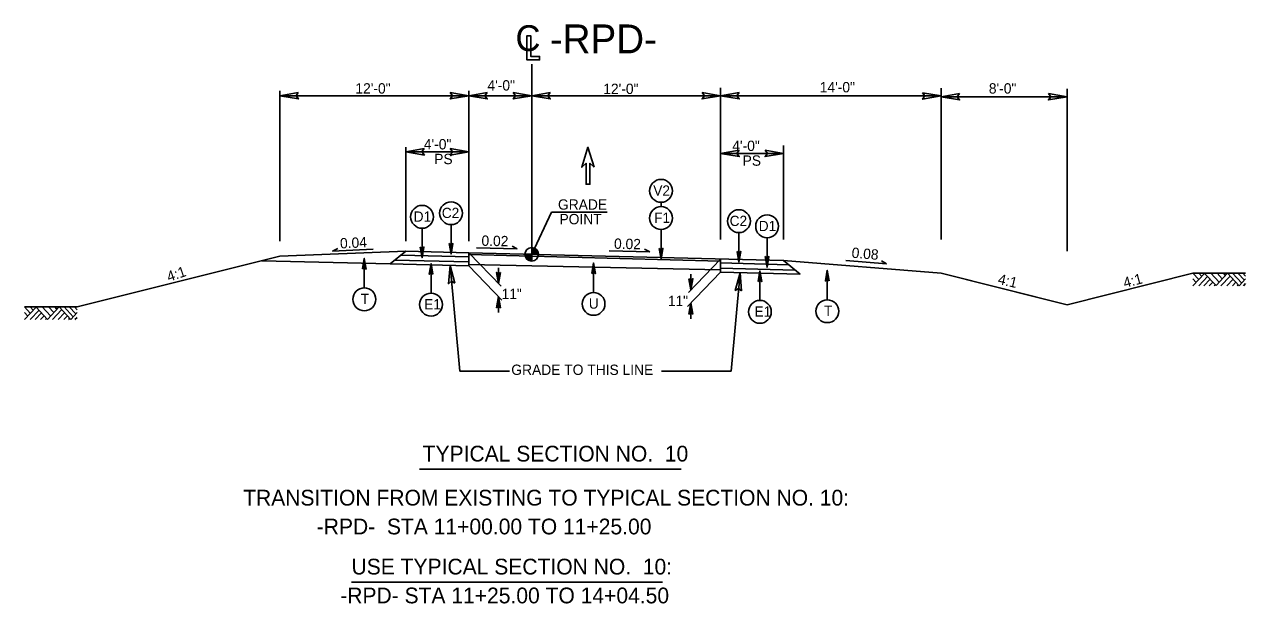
# Model space of a CAD drawing. Extents: x 1901582 to 1902252, y 193723 to 194156.
# Drawn here: x 1902172.2 to 1902249.8, y 193731.2 to 193767.9 of the extents above; entities that cross this region are included whole.
import ezdxf

# ---------------------------------------------------------------- set-up
doc = ezdxf.new("R2010")
doc.units = 0
for name, color, linetype in [('Old_Level_1', 7, 'Continuous'), ('Old_Level_11', 7, 'Continuous'), ('Old_Level_2', 7, 'Continuous'), ('Old_Level_20', 7, 'Continuous'), ('Prop Dimension', 7, 'Continuous'), ('Prop Dimension Text', 7, 'Continuous'), ('Typical Grade Point Symbol CELL', 7, 'Continuous'), ('Typical Pavement Slope Information CELL', 7, 'Continuous'), ('Typical Slope Point Local CELL', 7, 'Continuous'), ('Typical Terminator CELL', 7, 'Continuous'), ('Typical Text Centerline CELL', 7, 'Continuous'), ('Typical Text General CELL', 7, 'Continuous'), ('Typical Text Grade Point CELL', 7, 'Continuous')]:
    doc.layers.add(name, color=color, linetype=linetype)

# ---------------------------------------------------------------- blocks, each defined once
blk = doc.blocks.new('TERMINATOR')
at = {"layer": 'Typical Terminator CELL'}
blk.add_lwpolyline([(-0.469, 0.081), (0, 0), (-0.471, -0.083), (-0.411, 0)], close=True, dxfattribs=at)

msp = doc.modelspace()

# ---------------------------------------------------------------- linework, layer by layer
at = {"layer": 'Old_Level_1'}
for p, q in [((1902230.409, 193763.35), (1902238.409, 193763.35)), ((1902238.409, 193753.553), (1902238.409, 193763.85)), ((1902188.408, 193753.223), (1902175.527, 193750.002)), ((1902196.408, 193753.543), (1902188.408, 193753.223)), ((1902196.413, 193753.543), (1902195.42, 193752.734)), ((1902196.115, 193753.3), (1902200.403, 193753.193)), ((1902196.408, 193753.543), (1902200.409, 193753.443)), ((1902216.409, 193752.905), (1902200.408, 193753.327)), ((1902200.409, 193753.443), (1902200.409, 193752.609)), ((1902200.409, 193753.443), (1902220.409, 193752.943)), ((1902200.409, 193753.443), (1902202.457, 193751.326)), ((1902187.268, 193752.938), (1902195.42, 193752.734)), ((1902195.42, 193752.734), (1902200.409, 193752.609)), ((1902195.718, 193752.976), (1902200.394, 193752.86)), ((1902199.218, 193752.639), (1902199.834, 193745.929)), ((1902200.409, 193752.609), (1902202.515, 193750.433)), ((1902202.3, 193752.489), (1902202.3, 193751.489)), ((1902216.409, 193753.043), (1902214.36, 193750.926)), ((1902216.4, 193752.459), (1902221.149, 193752.341)), ((1902216.409, 193752.219), (1902216.409, 193753.043)), ((1902216.409, 193752.793), (1902220.727, 193752.685)), ((1902220.41, 193752.943), (1902230.409, 193752.143)), ((1902220.41, 193752.943), (1902221.466, 193752.083)), ((1902216.409, 193752.209), (1902214.302, 193750.033)), ((1902214.518, 193752.089), (1902214.518, 193751.089)), ((1902216.394, 193752.209), (1902221.466, 193752.083)), ((1902217.64, 193752.178), (1902217.066, 193745.929)), ((1902230.409, 193752.143), (1902236.73, 193750.562)), ((1902202.3, 193750.656), (1902202.3, 193749.656)), ((1902214.518, 193750.256), (1902214.518, 193749.256)), ((1902203.002, 193745.929), (1902199.834, 193745.929)), ((1902217.066, 193745.929), (1902212.643, 193745.929))]:
    msp.add_line(p, q, dxfattribs=at)
for points in [[(1902216.409, 193752.367), (1902200.409, 193752.687)], [(1902230.409, 193752.143), (1902238.409, 193750.143)], [(1902246.409, 193752.143), (1902238.409, 193750.143)], [(1902246.409, 193752.143), (1902249.751, 193752.143)], [(1902172.185, 193750.002), (1902175.527, 193750.002)]]:
    msp.add_lwpolyline(points, dxfattribs=at)
at = {"layer": 'Old_Level_11'}
for p, q in [((1902204.409, 193753.343), (1902204.409, 193765.415)), ((1902212.623, 193756.647), (1902212.623, 193756.369)), ((1902197.443, 193754.998), (1902197.443, 193753.124)), ((1902199.285, 193755.229), (1902199.285, 193753.355)), ((1902212.623, 193754.919), (1902212.623, 193753.045)), ((1902217.569, 193754.723), (1902217.569, 193752.849)), ((1902219.359, 193754.398), (1902219.359, 193752.524)), ((1902193.775, 193751.211), (1902193.775, 193753.085)), ((1902198.013, 193750.878), (1902198.013, 193752.753)), ((1902208.337, 193750.921), (1902208.337, 193752.796)), ((1902218.902, 193750.418), (1902218.902, 193752.292)), ((1902223.182, 193750.456), (1902223.182, 193752.33)), ((1902246.409, 193752.143), (1902246.784, 193751.74)), ((1902246.409, 193751.338), (1902247.151, 193752.135)), ((1902246.409, 193751.781), (1902246.615, 193751.559)), ((1902246.783, 193751.338), (1902247.337, 193751.934)), ((1902246.784, 193752.143), (1902246.971, 193751.942)), ((1902247.092, 193751.338), (1902247.493, 193751.767)), ((1902247.151, 193752.135), (1902247.875, 193751.356)), ((1902247.439, 193751.338), (1902247.666, 193751.581)), ((1902247.542, 193752.143), (1902248.075, 193751.57)), ((1902247.875, 193751.356), (1902248.606, 193752.142)), ((1902247.94, 193752.143), (1902248.273, 193751.784)), ((1902248.185, 193751.338), (1902248.771, 193751.966)), ((1902248.342, 193752.143), (1902248.475, 193752)), ((1902248.555, 193751.338), (1902248.955, 193751.767)), ((1902248.606, 193752.142), (1902249.347, 193751.346)), ((1902248.921, 193751.338), (1902249.138, 193751.571)), ((1902248.928, 193752.143), (1902249.508, 193751.52)), ((1902249.261, 193752.143), (1902249.675, 193751.699)), ((1902249.347, 193751.346), (1902249.751, 193751.781)), ((1902249.581, 193752.143), (1902249.751, 193751.96)), ((1902247.75, 193751.338), (1902247.821, 193751.414)), ((1902249.216, 193751.338), (1902249.285, 193751.412)), ((1902249.617, 193751.338), (1902249.751, 193751.481)), ((1902172.185, 193750.002), (1902172.56, 193749.599)), ((1902172.185, 193749.197), (1902172.927, 193749.994)), ((1902172.56, 193750.002), (1902172.747, 193749.801)), ((1902172.927, 193749.994), (1902173.651, 193749.215)), ((1902173.318, 193750.002), (1902173.851, 193749.429)), ((1902173.651, 193749.215), (1902174.382, 193750.001)), ((1902173.716, 193750.002), (1902174.049, 193749.643)), ((1902174.118, 193750.002), (1902174.251, 193749.859)), ((1902174.382, 193750.001), (1902175.123, 193749.205)), ((1902174.704, 193750.002), (1902175.284, 193749.379)), ((1902175.037, 193750.002), (1902175.451, 193749.558)), ((1902175.357, 193750.002), (1902175.527, 193749.819)), ((1902172.185, 193749.64), (1902172.391, 193749.418)), ((1902172.559, 193749.197), (1902173.113, 193749.793)), ((1902172.868, 193749.197), (1902173.269, 193749.626)), ((1902173.215, 193749.197), (1902173.442, 193749.44)), ((1902173.526, 193749.197), (1902173.597, 193749.273)), ((1902173.961, 193749.197), (1902174.547, 193749.825)), ((1902174.331, 193749.197), (1902174.731, 193749.626)), ((1902174.697, 193749.197), (1902174.914, 193749.43)), ((1902174.992, 193749.197), (1902175.061, 193749.271)), ((1902175.123, 193749.205), (1902175.527, 193749.64)), ((1902175.393, 193749.197), (1902175.527, 193749.34)), ((1902197.27, 193739.697), (1902213.896, 193739.697)), ((1902192.962, 193732.525), (1902212.705, 193732.525))]:
    msp.add_line(p, q, dxfattribs=at)
for points in [[(1902199.169, 193754.026), (1902199.285, 193753.355), (1902199.404, 193754.03), (1902199.285, 193753.944)], [(1902193.66, 193752.413), (1902193.775, 193753.085), (1902193.895, 193752.41), (1902193.775, 193752.495)], [(1902197.327, 193753.795), (1902197.443, 193753.124), (1902197.562, 193753.799), (1902197.443, 193753.713)], [(1902212.508, 193753.716), (1902212.623, 193753.045), (1902212.743, 193753.72), (1902212.623, 193753.634)], [(1902217.453, 193753.521), (1902217.569, 193752.849), (1902217.688, 193753.524), (1902217.569, 193753.438)], [(1902219.243, 193753.195), (1902219.359, 193752.524), (1902219.478, 193753.199), (1902219.359, 193753.113)], [(1902198.129, 193752.081), (1902198.013, 193752.753), (1902197.894, 193752.077), (1902198.013, 193752.163)], [(1902208.221, 193752.124), (1902208.337, 193752.796), (1902208.456, 193752.12), (1902208.337, 193752.206)], [(1902218.786, 193751.62), (1902218.902, 193752.292), (1902219.021, 193751.617), (1902218.902, 193751.702)], [(1902223.297, 193751.659), (1902223.182, 193752.33), (1902223.062, 193751.655), (1902223.182, 193751.741)]]:
    msp.add_lwpolyline(points, close=True, dxfattribs=at)
for centre in [(1902212.623, 193757.373), (1902197.443, 193755.723), (1902199.285, 193755.954), (1902212.623, 193755.644), (1902217.569, 193755.448), (1902219.359, 193755.123), (1902193.775, 193750.486), (1902198.013, 193750.153), (1902208.337, 193750.196), (1902218.902, 193749.692), (1902223.182, 193749.731)]:
    msp.add_circle(centre, 0.725, dxfattribs=at)
at = {"layer": 'Prop Dimension'}
for p, q in [((1902216.409, 193754.278), (1902216.409, 193763.915)), ((1902188.408, 193754.178), (1902188.409, 193763.715)), ((1902200.409, 193763.415), (1902188.409, 193763.415)), ((1902200.408, 193754.178), (1902200.409, 193763.715)), ((1902204.409, 193763.415), (1902200.409, 193763.415)), ((1902216.409, 193763.415), (1902204.409, 193763.415)), ((1902216.409, 193763.415), (1902230.409, 193763.4)), ((1902230.409, 193754.277), (1902230.409, 193763.9)), ((1902196.408, 193754.178), (1902196.409, 193760.152)), ((1902220.409, 193754.277), (1902220.409, 193760.252)), ((1902200.409, 193759.852), (1902196.409, 193759.852)), ((1902216.409, 193759.752), (1902220.409, 193759.752))]:
    msp.add_line(p, q, dxfattribs=at)
msp.add_lwpolyline([(1902208.377, 193758.87), (1902208.106, 193759.12), (1902208.106, 193757.787), (1902207.856, 193757.787), (1902207.856, 193759.12), (1902207.585, 193758.87), (1902207.981, 193760.141)], close=True, dxfattribs=at)
msp.add_lwpolyline([(1902208.377, 193758.87), (1902208.106, 193759.12), (1902208.106, 193757.787), (1902207.856, 193757.787), (1902207.856, 193759.12), (1902207.585, 193758.87), (1902207.981, 193760.141)], close=True, dxfattribs=at)
at = {"layer": 'Typical Grade Point Symbol CELL'}
for p, q in [((1902203.979, 193753.343), (1902204.409, 193753.343)), ((1902204.408, 193752.913), (1902204.409, 193753.343)), ((1902204.409, 193753.343), (1902204.408, 193752.913)), ((1902204.409, 193753.343), (1902204.409, 193753.772)), ((1902204.839, 193753.343), (1902204.409, 193753.343))]:
    msp.add_line(p, q, dxfattribs=at)
for points in [[(1902203.981, 193753.343), (1902203.981, 193753.296)], [(1902203.99, 193753.343), (1902203.99, 193753.245)], [(1902203.998, 193753.343), (1902203.998, 193753.215)], [(1902204.007, 193753.343), (1902204.007, 193753.189)], [(1902204.015, 193753.343), (1902204.015, 193753.169)], [(1902204.024, 193753.343), (1902204.024, 193753.151)], [(1902204.033, 193753.343), (1902204.033, 193753.135)], [(1902204.041, 193753.343), (1902204.041, 193753.119)], [(1902204.05, 193753.343), (1902204.05, 193753.106)], [(1902204.058, 193753.343), (1902204.058, 193753.093)], [(1902204.067, 193753.343), (1902204.067, 193753.082)], [(1902204.076, 193753.343), (1902204.076, 193753.071)], [(1902204.084, 193753.343), (1902204.084, 193753.061)], [(1902204.093, 193753.343), (1902204.093, 193753.051)], [(1902204.101, 193753.343), (1902204.101, 193753.042)], [(1902204.11, 193753.343), (1902204.11, 193753.033)], [(1902204.119, 193753.343), (1902204.119, 193753.026)], [(1902204.127, 193753.343), (1902204.127, 193753.018)], [(1902204.136, 193753.343), (1902204.136, 193753.01)], [(1902204.144, 193753.343), (1902204.144, 193753.004)], [(1902204.153, 193753.343), (1902204.153, 193752.997)], [(1902204.162, 193753.343), (1902204.162, 193752.991)], [(1902204.17, 193753.343), (1902204.17, 193752.986)], [(1902204.179, 193753.343), (1902204.179, 193752.98)], [(1902204.187, 193753.343), (1902204.187, 193752.974)], [(1902204.196, 193753.343), (1902204.196, 193752.969)], [(1902204.205, 193753.343), (1902204.205, 193752.965)], [(1902204.213, 193753.343), (1902204.213, 193752.96)], [(1902204.222, 193753.343), (1902204.222, 193752.956)], [(1902204.23, 193753.343), (1902204.23, 193752.952)], [(1902204.239, 193753.343), (1902204.239, 193752.948)], [(1902204.247, 193753.343), (1902204.247, 193752.944)], [(1902204.256, 193753.343), (1902204.256, 193752.941)], [(1902204.265, 193753.343), (1902204.265, 193752.938)], [(1902204.273, 193753.343), (1902204.273, 193752.935)], [(1902204.282, 193753.343), (1902204.282, 193752.932)], [(1902204.29, 193753.343), (1902204.29, 193752.93)], [(1902204.299, 193753.343), (1902204.299, 193752.927)], [(1902204.308, 193753.343), (1902204.308, 193752.925)], [(1902204.316, 193753.343), (1902204.316, 193752.923)], [(1902204.325, 193753.343), (1902204.325, 193752.922)], [(1902204.333, 193753.343), (1902204.333, 193752.92)], [(1902204.342, 193753.343), (1902204.342, 193752.919)], [(1902204.351, 193753.343), (1902204.351, 193752.917)], [(1902204.359, 193753.343), (1902204.359, 193752.916)], [(1902204.368, 193753.343), (1902204.368, 193752.915)], [(1902204.376, 193753.343), (1902204.376, 193752.914)], [(1902204.385, 193753.343), (1902204.385, 193752.914)], [(1902204.394, 193753.343), (1902204.394, 193752.913)], [(1902204.402, 193753.343), (1902204.402, 193752.913), (1902204.402, 193752.913)], [(1902204.413, 193753.772), (1902204.413, 193753.772), (1902204.413, 193753.343)], [(1902204.421, 193753.772), (1902204.421, 193753.343)], [(1902204.43, 193753.771), (1902204.43, 193753.343)], [(1902204.438, 193753.771), (1902204.438, 193753.343)], [(1902204.447, 193753.77), (1902204.447, 193753.343)], [(1902204.456, 193753.769), (1902204.456, 193753.343)], [(1902204.464, 193753.769), (1902204.464, 193753.343)], [(1902204.473, 193753.768), (1902204.473, 193753.343)], [(1902204.481, 193753.767), (1902204.481, 193753.343)], [(1902204.49, 193753.765), (1902204.49, 193753.343)], [(1902204.499, 193753.763), (1902204.499, 193753.343)], [(1902204.507, 193753.761), (1902204.507, 193753.343)], [(1902204.516, 193753.759), (1902204.516, 193753.343)], [(1902204.524, 193753.756), (1902204.524, 193753.343)], [(1902204.533, 193753.754), (1902204.533, 193753.343)], [(1902204.542, 193753.751), (1902204.542, 193753.343)], [(1902204.55, 193753.748), (1902204.55, 193753.343)], [(1902204.559, 193753.746), (1902204.559, 193753.343)], [(1902204.567, 193753.742), (1902204.567, 193753.343)], [(1902204.576, 193753.738), (1902204.576, 193753.343)], [(1902204.585, 193753.734), (1902204.585, 193753.343)], [(1902204.593, 193753.73), (1902204.593, 193753.343)], [(1902204.602, 193753.727), (1902204.602, 193753.343)], [(1902204.61, 193753.722), (1902204.61, 193753.343)], [(1902204.619, 193753.717), (1902204.619, 193753.343)], [(1902204.628, 193753.712), (1902204.628, 193753.343)], [(1902204.636, 193753.707), (1902204.636, 193753.343)], [(1902204.645, 193753.702), (1902204.645, 193753.343)], [(1902204.653, 193753.696), (1902204.653, 193753.343)], [(1902204.662, 193753.689), (1902204.662, 193753.343)], [(1902204.67, 193753.684), (1902204.67, 193753.343)], [(1902204.679, 193753.677), (1902204.679, 193753.343)], [(1902204.688, 193753.669), (1902204.688, 193753.343)], [(1902204.696, 193753.662), (1902204.696, 193753.343)], [(1902204.705, 193753.654), (1902204.705, 193753.343)], [(1902204.713, 193753.645), (1902204.713, 193753.343)], [(1902204.722, 193753.637), (1902204.722, 193753.343)], [(1902204.731, 193753.627), (1902204.731, 193753.343)], [(1902204.739, 193753.617), (1902204.739, 193753.343)], [(1902204.748, 193753.606), (1902204.748, 193753.343)], [(1902204.756, 193753.595), (1902204.756, 193753.343)], [(1902204.765, 193753.582), (1902204.765, 193753.343)], [(1902204.774, 193753.569), (1902204.774, 193753.343)], [(1902204.782, 193753.555), (1902204.782, 193753.343)], [(1902204.791, 193753.539), (1902204.791, 193753.343)], [(1902204.799, 193753.521), (1902204.799, 193753.343)], [(1902204.808, 193753.501), (1902204.808, 193753.343)], [(1902204.817, 193753.477), (1902204.817, 193753.343)], [(1902204.825, 193753.448), (1902204.825, 193753.343)], [(1902204.834, 193753.404), (1902204.834, 193753.343)]]:
    msp.add_lwpolyline(points, dxfattribs=at)
msp.add_circle((1902204.408, 193753.343), 0.43, dxfattribs=at)
for start, end in [(179.99048, 269.99048), (359.99048, 89.99048)]:
    msp.add_arc((1902204.408, 193753.343), 0.43, start, end, dxfattribs=at)
at = {"layer": 'Typical Pavement Slope Information CELL'}
for p, q in [((1902203.488, 193753.689), (1902203.156, 193753.857)), ((1902191.757, 193753.539), (1902192.085, 193753.716)), ((1902194.341, 193753.668), (1902191.757, 193753.539)), ((1902200.901, 193753.752), (1902203.488, 193753.689)), ((1902209.319, 193753.563), (1902211.906, 193753.5)), ((1902211.906, 193753.5), (1902211.574, 193753.668)), ((1902224.368, 193752.947), (1902226.948, 193752.741)), ((1902226.948, 193752.741), (1902226.625, 193752.927))]:
    msp.add_line(p, q, dxfattribs=at)
at = {"layer": 'Typical Terminator CELL'}
for points in [[(1902189.581, 193763.617), (1902188.409, 193763.415), (1902189.587, 193763.207), (1902189.438, 193763.415)], [(1902199.237, 193763.617), (1902200.409, 193763.415), (1902199.231, 193763.207), (1902199.381, 193763.415)], [(1902201.581, 193763.617), (1902200.409, 193763.415), (1902201.587, 193763.207), (1902201.438, 193763.415)], [(1902203.237, 193763.617), (1902204.409, 193763.415), (1902203.231, 193763.207), (1902203.381, 193763.415)], [(1902205.581, 193763.617), (1902204.409, 193763.415), (1902205.587, 193763.207), (1902205.438, 193763.415)], [(1902215.237, 193763.617), (1902216.409, 193763.415), (1902215.231, 193763.207), (1902215.381, 193763.415)], [(1902217.581, 193763.617), (1902216.409, 193763.415), (1902217.587, 193763.207), (1902217.438, 193763.415)], [(1902229.237, 193763.602), (1902230.409, 193763.4), (1902229.231, 193763.192), (1902229.381, 193763.4)], [(1902231.581, 193763.552), (1902230.409, 193763.35), (1902231.587, 193763.142), (1902231.438, 193763.35)], [(1902237.237, 193763.552), (1902238.409, 193763.35), (1902237.231, 193763.142), (1902237.381, 193763.35)], [(1902197.58, 193760.054), (1902196.409, 193759.852), (1902197.587, 193759.644), (1902197.437, 193759.852)], [(1902199.237, 193760.054), (1902200.409, 193759.852), (1902199.23, 193759.644), (1902199.38, 193759.852)], [(1902217.581, 193759.954), (1902216.409, 193759.752), (1902217.587, 193759.544), (1902217.437, 193759.752)], [(1902219.237, 193759.954), (1902220.409, 193759.752), (1902219.231, 193759.544), (1902219.381, 193759.752)], [(1902199.517, 193751.522), (1902199.218, 193752.639), (1902199.121, 193751.479), (1902199.309, 193751.643)], [(1902217.731, 193751.025), (1902217.64, 193752.178), (1902217.333, 193751.055), (1902217.549, 193751.182)]]:
    msp.add_lwpolyline(points, close=True, dxfattribs=at)
at = {"layer": 'Typical Text Centerline CELL'}
msp.add_lwpolyline([(1902204.101, 193765.91), (1902204.101, 193765.686), (1902204.909, 193765.686), (1902204.91, 193765.909), (1902204.35, 193765.91), (1902204.351, 193767.223), (1902204.102, 193767.223)], close=True, dxfattribs=at)
at = {"layer": 'Typical Text Grade Point CELL'}
for p in [(1902204.409, 193753.343), (1902209.209, 193756.012)]:
    msp.add_line(p, (1902205.671, 193756.012), dxfattribs=at)

# ---------------------------------------------------------------- block references
at = {"layer": 'Old_Level_1', "xscale": 1.5}
for p, yscale, rotation in [((1902202.3, 193751.489), 1.5, -90), ((1902214.518, 193751.089), -1.5, -90), ((1902202.3, 193750.656), 1.5, 90), ((1902214.518, 193750.256), -1.5, 90)]:
    msp.add_blockref('TERMINATOR', p, dxfattribs=dict(at, yscale=yscale, rotation=rotation))

# ---------------------------------------------------------------- texts
at = {"layer": 'Old_Level_1'}
for s, p in [('8\'-0"', (1902233.444, 193763.548)), ('4\'-0"', (1902197.557, 193760.004)), ('4\'-0"', (1902217.147, 193759.904))]:
    msp.add_text(s, height=0.656, dxfattribs=at).set_placement(p)
msp.add_text('4:1', height=0.656, rotation=14.75437, dxfattribs=at).set_placement((1902242.075, 193751.202))
at = {"layer": 'Old_Level_11'}
for s, p in [('TYPICAL SECTION NO.  10', (1902197.481, 193740.191)), ('TRANSITION FROM EXISTING TO TYPICAL SECTION NO. 10: ', (1902186.077, 193737.396)), ('-RPD-  STA 11+00.00 TO 11+25.00', (1902190.753, 193735.565)), ('USE TYPICAL SECTION NO.  10:', (1902192.962, 193733.019)), ('-RPD- STA 11+25.00 TO 14+04.50', (1902192.245, 193731.187))]:
    msp.add_text(s, height=1, dxfattribs=at).set_placement(p)
at = {"layer": 'Old_Level_2'}
for s, rotation, p in [('0.04', 2.64907, (1902192.246, 193753.712)), ('0.02', 358.80842, (1902201.212, 193753.887)), ('0.02', 358.80842, (1902209.63, 193753.697))]:
    msp.add_text(s, height=0.656, rotation=rotation, dxfattribs=at).set_placement(p)
at = {"layer": 'Old_Level_20'}
for s, height, p in [('V2', 0.6491, (1902212.128, 193757.066)), ('C2', 0.6491, (1902198.696, 193755.648)), ('D1', 0.6491, (1902196.91, 193755.417)), ('F1', 0.6491, (1902212.182, 193755.338)), ('C2', 0.6491, (1902216.98, 193755.142)), ('D1', 0.6491, (1902218.827, 193754.817)), ('T', 0.649, (1902193.548, 193750.192)), ('11"', 0.6491, (1902202.499, 193750.51)), ('E1', 0.6491, (1902197.579, 193749.85)), ('U', 0.649, (1902208.033, 193749.893)), ('11"', 0.6491, (1902213.059, 193750.061)), ('E1', 0.6491, (1902218.556, 193749.389)), ('T', 0.649, (1902222.971, 193749.438))]:
    msp.add_text(s, height=height, dxfattribs=at).set_placement(p)
at = {"layer": 'Prop Dimension Text'}
for s, p in [('12\'-0"', (1902193.208, 193763.55)), ('4\'-0"', (1902201.596, 193763.742)), ('12\'-0"', (1902208.953, 193763.522)), ('14\'-0"', (1902222.704, 193763.626)), ('PS', (1902198.213, 193759.067)), ('PS', (1902217.802, 193758.967))]:
    msp.add_text(s, height=0.656, dxfattribs=at).set_placement(p)
at = {"layer": 'Typical Pavement Slope Information CELL'}
msp.add_text('0.08', height=0.656, rotation=355.19472, dxfattribs=at).set_placement((1902224.708, 193753.131))
at = {"layer": 'Typical Slope Point Local CELL'}
for rotation, p in [(18.90137, (1902181.362, 193751.589)), (346.9803, (1902233.977, 193751.476))]:
    msp.add_text('4:1', height=0.656, rotation=rotation, dxfattribs=at).set_placement(p)
at = {"layer": 'Typical Text Centerline CELL'}
msp.add_text('C', height=1.64, dxfattribs=at).set_placement((1902203.379, 193766.247))
msp.add_text('-RPD-', height=1.8323, rotation=0.00002, dxfattribs=at).set_placement((1902205.557, 193766.105))
at = {"layer": 'Typical Text General CELL'}
msp.add_text('GRADE TO THIS LINE', height=0.656, dxfattribs=at).set_placement((1902203.111, 193745.687))
at = {"layer": 'Typical Text Grade Point CELL'}
for s, p in [('GRADE', (1902206.075, 193756.178)), ('POINT', (1902206.171, 193755.251))]:
    msp.add_text(s, height=0.656, rotation=0, dxfattribs=at).set_placement(p)

doc.saveas('drawing.dxf')
